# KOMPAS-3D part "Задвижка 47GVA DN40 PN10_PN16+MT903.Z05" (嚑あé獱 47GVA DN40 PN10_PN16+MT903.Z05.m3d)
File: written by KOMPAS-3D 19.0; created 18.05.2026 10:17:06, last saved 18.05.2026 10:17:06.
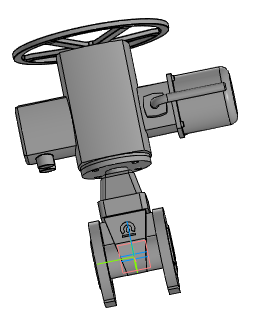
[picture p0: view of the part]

Document properties: Автор: Энергия; Полное имя файла: ..\Задвижка 47GVA DN50_DN1000+MT903.Z\Задвижка 47GVA DN40 PN10_PN16+MT903.Z05.a3d

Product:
- Part/product: Задвижка 47GVA DN40 PN10_PN16+MT903.Z05
    Масса: 64.4182
  - Body: Электропривод MT903.Z05-15
      Масса: 49.8062
  - Body: Задвижка 47GVA DN40 PN10_PN16 без исполн. мех.
      Масса: 14.612

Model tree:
1. Операция без истории:1
2. Операция без истории:2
